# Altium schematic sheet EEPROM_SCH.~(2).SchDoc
size D
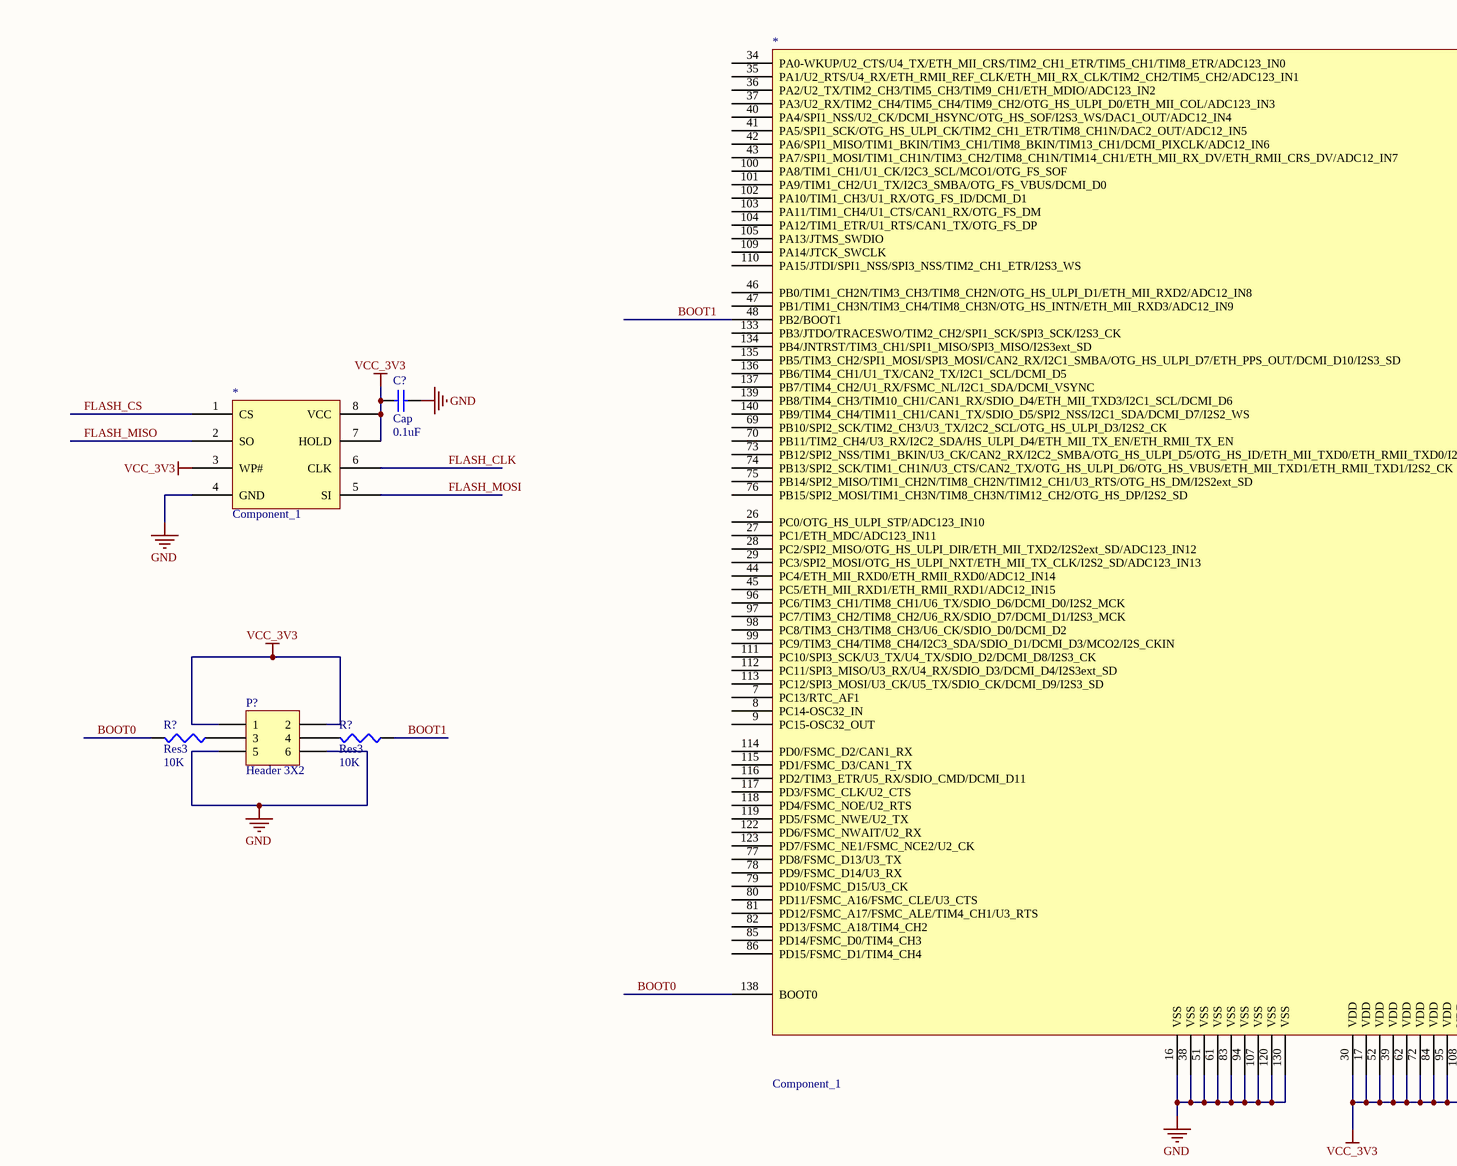
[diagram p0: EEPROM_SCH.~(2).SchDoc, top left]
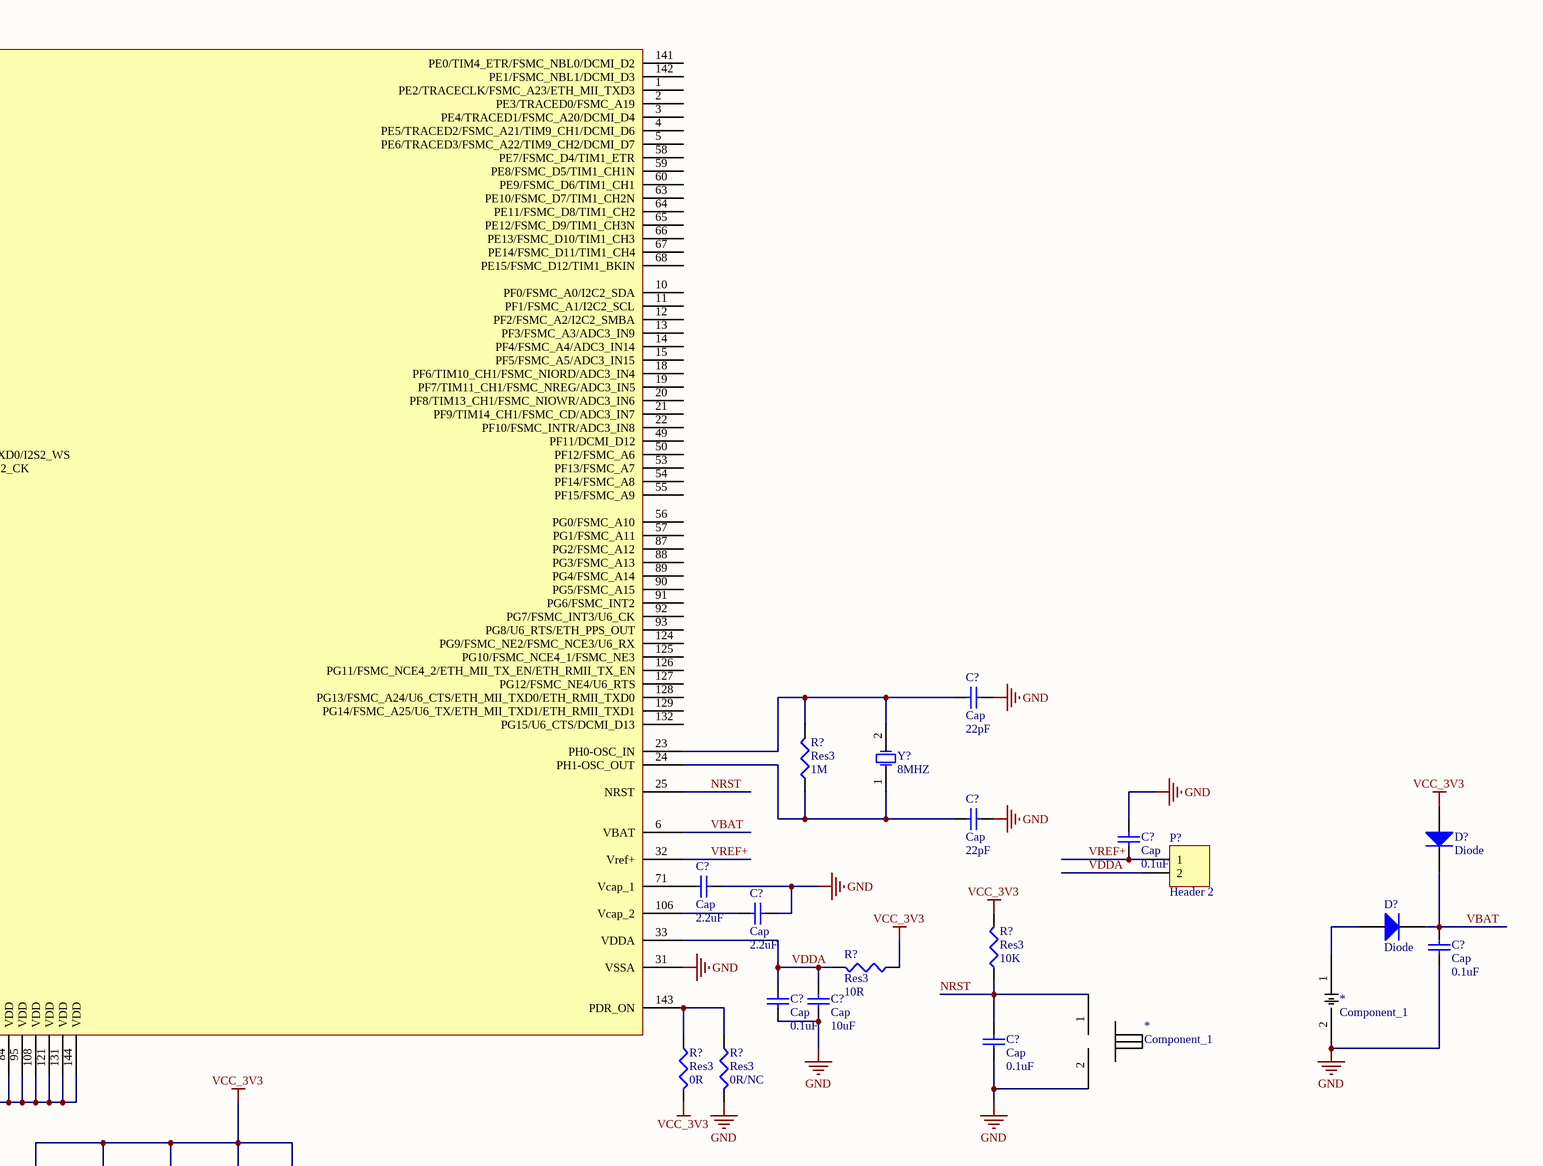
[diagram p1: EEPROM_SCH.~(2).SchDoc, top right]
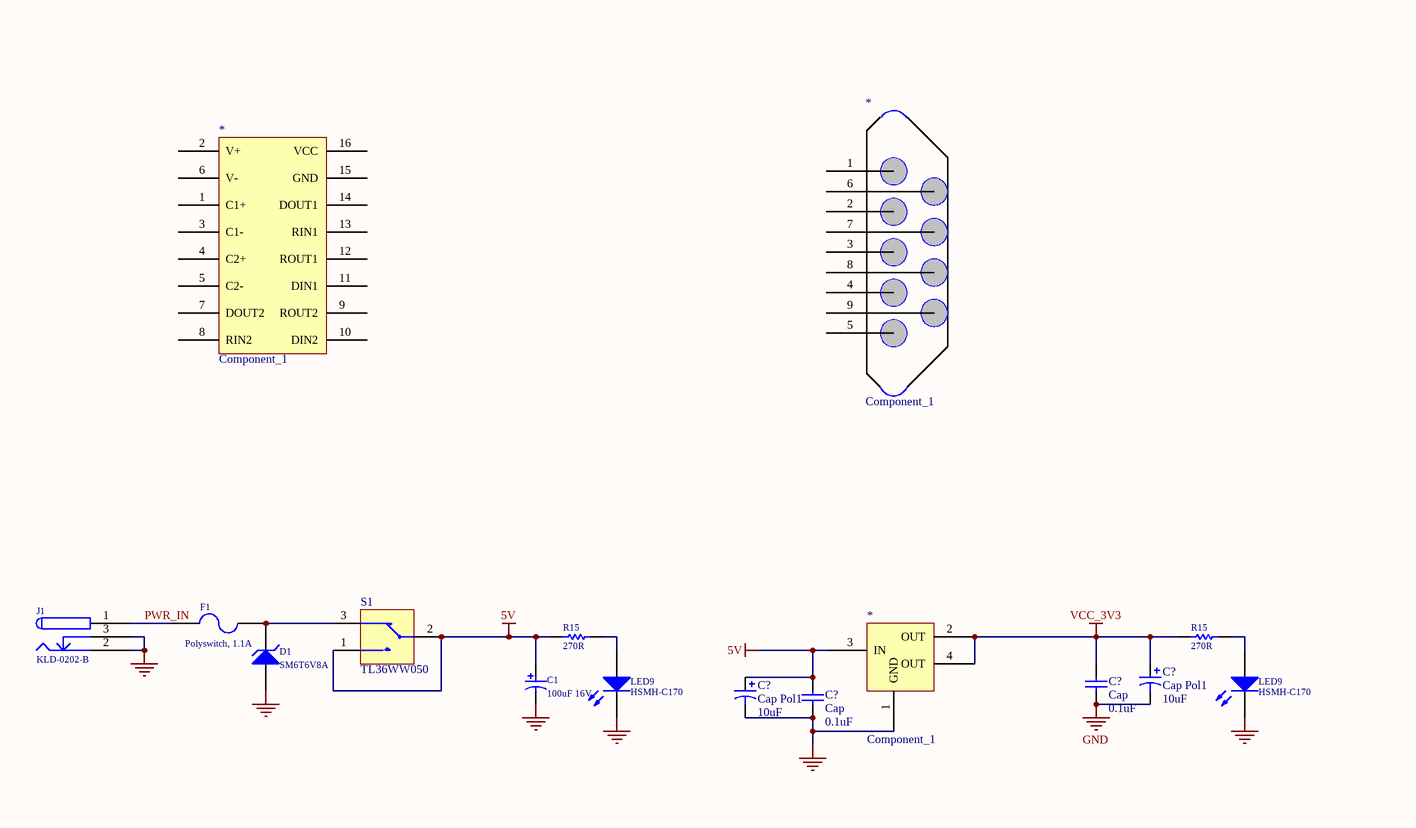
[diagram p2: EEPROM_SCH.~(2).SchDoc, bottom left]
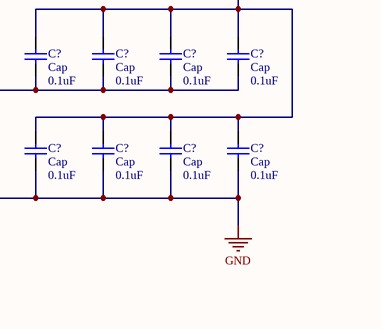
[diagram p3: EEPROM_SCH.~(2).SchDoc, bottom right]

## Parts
(Parts that share a designator on the sheet are numbered #1, #2 ... from top to bottom, then left to right.)
*#1  Component_1
*#2  Component_1
*#3  Component_1
*#4  Component_1
*#5  Component_1
*#6  Component_1
*#7  Component_1
C1  100uF 16V  [CAPPR2-5X6.8]
C?#1  Cap  value 0.1uF  [RAD-0.3]
C?#2  Cap  value 22pF  [RAD-0.3]
C?#3  Cap  value 22pF  [RAD-0.3]
C?#4  Cap  value 0.1uF  [RAD-0.3]
C?#5  Cap  value 2.2uF  [RAD-0.3]
C?#6  Cap  value 2.2uF  [RAD-0.3]
C?#7  Cap  value 0.1uF  [RAD-0.3]
C?#8  Cap  value 0.1uF  [RAD-0.3]
C?#9  Cap  value 10uF  [RAD-0.3]
C?#10  Cap  value 0.1uF  [RAD-0.3]
C?#11  Cap  value 0.1uF  [RAD-0.3]
C?#12  Cap  value 0.1uF  [RAD-0.3]
C?#13  Cap  value 0.1uF  [RAD-0.3]
C?#14  Cap  value 0.1uF  [RAD-0.3]
C?#15  Cap  value 0.1uF  [RAD-0.3]
C?#16  Cap  value 0.1uF  [RAD-0.3]
C?#17  Cap  value 0.1uF  [RAD-0.3]
C?#18  Cap  value 0.1uF  [RAD-0.3]
C?#19  Cap  value 0.1uF  [RAD-0.3]
C?#20  Cap Pol1  value 10uF  [RB7.6-15]
C?#21  Cap Pol1  value 10uF  [RB7.6-15]
C?#22  Cap  value 0.1uF  [RAD-0.3]
D1  SM6T6V8A  [DO214]
D?#1  Diode  [SMC]
D?#2  Diode  [SMC]
F1  Polyswitch, 1.1A  [RUE160_0.2]
J1  KLD-0202-B  [KLD-0202]
LED9#1  HSMH-C170  [SMD _LED]
LED9#2  HSMH-C170  [SMD _LED]
P?#1  Header 3X2  [HDR2X3]
P?#2  Header 2  [HDR1X2]
R15#1  270R  [CR2012-0805]
R15#2  270R  [CR2012-0805]
R?#1  Res3  value 10K  [J1-0603]
R?#2  Res3  value 10K  [J1-0603]
R?#3  Res3  value 1M  [J1-0603]
R?#4  Res3  value 10K  [J1-0603]
R?#5  Res3  value 10R  [J1-0603]
R?#6  Res3  value 0R  [J1-0603]
R?#7  Res3  value 0R/NC  [J1-0603]
S1  TL36WW050  [PCB_SWITCH]
Y?  8MHZ  [R38]

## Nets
5V: *#7.3(IN) C1.1 C?#21.1 C?#22.1 R15#1.2 S1.1 S1.2
GND: *#1.16(VSS) *#1.31(VSSA) *#1.38(VSS) *#1.51(VSS) *#1.61(VSS) *#1.83(VSS) *#1.94(VSS) *#1.107(VSS) *#1.120(VSS) *#1.130(VSS) *#2.4(GND) *#3.2 *#4.2 *#7.1(GND) C1.2 C?#1.2 C?#2.1 C?#3.1 C?#4.1 C?#5.2 C?#6.2 C?#7.2 C?#8.2 C?#9.2 C?#10.2 C?#11.1 C?#12.1 C?#13.1 C?#14.1 C?#15.1 C?#16.1 C?#17.1 C?#18.1 C?#19.2 C?#20.2 C?#21.2 C?#22.2 D1.1(A) J1.2 J1.3 LED9#1.2(K) LED9#2.2(K) P?#1.5 P?#1.6 R?#7.2
VCC_3V3: *#1.17(VDD) *#1.30(VDD) *#1.39(VDD) *#1.52(VDD) *#1.62(VDD) *#1.72(VDD) *#1.84(VDD) *#1.95(VDD) *#1.108(VDD) *#1.121(VDD) *#1.131(VDD) *#1.144(VDD) *#2.3(WP#) *#2.7(HOLD) *#2.8(VCC) *#7.2(OUT) *#7.4(OUT) C?#1.1 C?#11.2 C?#12.2 C?#13.2 C?#14.2 C?#15.2 C?#16.2 C?#17.2 C?#18.2 C?#19.1 C?#20.1 D?#1.1(A) P?#1.1 P?#1.2 R15#2.2 R?#4.2 R?#5.1 R?#6.2
BOOT0: *#1.138(BOOT0) R?#1.2
BOOT1: *#1.48(PB2/BOOT1) R?#2.1
FLASH_CLK: *#2.6(CLK)
FLASH_CS: *#2.1(CS)
FLASH_MISO: *#2.2(SO)
FLASH_MOSI: *#2.5(SI)
NRST: *#1.25(NRST) *#3.1 C?#10.1 R?#4.1
PWR_IN: F1.1 J1.1
VBAT: *#1.6(VBAT) C?#7.1 D?#1.2(K) D?#2.2(K)
VDDA: *#1.33(VDDA) C?#8.1 C?#9.1 P?#2.2 R?#5.2
VREF+: *#1.32(Vref+) C?#4.2 P?#2.1
Net*#1_23: *#1.23(PH0-OSC_IN) C?#2.2 R?#3.2 Y?.2(OSC2)
Net*#1_24: *#1.24(PH1-OSC_OUT) C?#3.2 R?#3.1 Y?.1(OSC1)
Net*#1_71: *#1.71(Vcap_1) C?#5.1
Net*#1_106: *#1.106(Vcap_2) C?#6.1
Net*#1_143: *#1.143(PDR_ON) R?#6.1 R?#7.1
Net*#4_1: *#4.1 D?#2.1(A)
NetD1_2: D1.2(K) F1.2 S1.3
NetLED9#1_1: LED9#1.1(A) R15#1.1
NetLED9#2_1: LED9#2.1(A) R15#2.1
NetP?#1_3: P?#1.3 R?#1.1
NetP?#1_4: P?#1.4 R?#2.2

Not connected (* = marked no-connect by the designer): *#1 1(PE2/TRACECLK/FSMC_A23/ETH_MII_TXD3) 2(PE3/TRACED0/FSMC_A19) 3(PE4/TRACED1/FSMC_A20/DCMI_D4) 4(PE5/TRACED2/FSMC_A21/TIM9_CH1/DCMI_D6) 5(PE6/TRACED3/FSMC_A22/TIM9_CH2/DCMI_D7) 7(PC13/RTC_AF1) 8(PC14-OSC32_IN) 9(PC15-OSC32_OUT) 10(PF0/FSMC_A0/I2C2_SDA) 11(PF1/FSMC_A1/I2C2_SCL) 12(PF2/FSMC_A2/I2C2_SMBA) 13(PF3/FSMC_A3/ADC3_IN9) 14(PF4/FSMC_A4/ADC3_IN14) 15(PF5/FSMC_A5/ADC3_IN15) 18(PF6/TIM10_CH1/FSMC_NIORD/ADC3_IN4) 19(PF7/TIM11_CH1/FSMC_NREG/ADC3_IN5) 20(PF8/TIM13_CH1/FSMC_NIOWR/ADC3_IN6) 21(PF9/TIM14_CH1/FSMC_CD/ADC3_IN7) 22(PF10/FSMC_INTR/ADC3_IN8) 26(PC0/OTG_HS_ULPI_STP/ADC123_IN10) 27(PC1/ETH_MDC/ADC123_IN11) 28(PC2/SPI2_MISO/OTG_HS_ULPI_DIR/ETH_MII_TXD2/I2S2ext_SD/ADC123_IN12) 29(PC3/SPI2_MOSI/OTG_HS_ULPI_NXT/ETH_MII_TX_CLK/I2S2_SD/ADC123_IN13) 34(PA0-WKUP/U2_CTS/U4_TX/ETH_MII_CRS/TIM2_CH1_ETR/TIM5_CH1/TIM8_ETR/ADC123_IN0) 35(PA1/U2_RTS/U4_RX/ETH_RMII_REF_CLK/ETH_MII_RX_CLK/TIM2_CH2/TIM5_CH2/ADC123_IN1) 36(PA2/U2_TX/TIM2_CH3/TIM5_CH3/TIM9_CH1/ETH_MDIO/ADC123_IN2) 37(PA3/U2_RX/TIM2_CH4/TIM5_CH4/TIM9_CH2/OTG_HS_ULPI_D0/ETH_MII_COL/ADC123_IN3) 40(PA4/SPI1_NSS/U2_CK/DCMI_HSYNC/OTG_HS_SOF/I2S3_WS/DAC1_OUT/ADC12_IN4) 41(PA5/SPI1_SCK/OTG_HS_ULPI_CK/TIM2_CH1_ETR/TIM8_CH1N/DAC2_OUT/ADC12_IN5) 42(PA6/SPI1_MISO/TIM1_BKIN/TIM3_CH1/TIM8_BKIN/TIM13_CH1/DCMI_PIXCLK/ADC12_IN6) 43(PA7/SPI1_MOSI/TIM1_CH1N/TIM3_CH2/TIM8_CH1N/TIM14_CH1/ETH_MII_RX_DV/ETH_RMII_CRS_DV/ADC12_IN7) 44(PC4/ETH_MII_RXD0/ETH_RMII_RXD0/ADC12_IN14) 45(PC5/ETH_MII_RXD1/ETH_RMII_RXD1/ADC12_IN15) 46(PB0/TIM1_CH2N/TIM3_CH3/TIM8_CH2N/OTG_HS_ULPI_D1/ETH_MII_RXD2/ADC12_IN8) 47(PB1/TIM1_CH3N/TIM3_CH4/TIM8_CH3N/OTG_HS_INTN/ETH_MII_RXD3/ADC12_IN9) 49(PF11/DCMI_D12) 50(PF12/FSMC_A6) 53(PF13/FSMC_A7) 54(PF14/FSMC_A8) 55(PF15/FSMC_A9) 56(PG0/FSMC_A10) 57(PG1/FSMC_A11) 58(PE7/FSMC_D4/TIM1_ETR) 59(PE8/FSMC_D5/TIM1_CH1N) 60(PE9/FSMC_D6/TIM1_CH1) 63(PE10/FSMC_D7/TIM1_CH2N) 64(PE11/FSMC_D8/TIM1_CH2) 65(PE12/FSMC_D9/TIM1_CH3N) 66(PE13/FSMC_D10/TIM1_CH3) 67(PE14/FSMC_D11/TIM1_CH4) 68(PE15/FSMC_D12/TIM1_BKIN) 69(PB10/SPI2_SCK/TIM2_CH3/U3_TX/I2C2_SCL/OTG_HS_ULPI_D3/I2S2_CK) 70(PB11/TIM2_CH4/U3_RX/I2C2_SDA/HS_ULPI_D4/ETH_MII_TX_EN/ETH_RMII_TX_EN) 73(PB12/SPI2_NSS/TIM1_BKIN/U3_CK/CAN2_RX/I2C2_SMBA/OTG_HS_ULPI_D5/OTG_HS_ID/ETH_MII_TXD0/ETH_RMII_TXD0/I2S2_WS) 74(PB13/SPI2_SCK/TIM1_CH1N/U3_CTS/CAN2_TX/OTG_HS_ULPI_D6/OTG_HS_VBUS/ETH_MII_TXD1/ETH_RMII_TXD1/I2S2_CK) 75(PB14/SPI2_MISO/TIM1_CH2N/TIM8_CH2N/TIM12_CH1/U3_RTS/OTG_HS_DM/I2S2ext_SD) 76(PB15/SPI2_MOSI/TIM1_CH3N/TIM8_CH3N/TIM12_CH2/OTG_HS_DP/I2S2_SD) 77(PD8/FSMC_D13/U3_TX) 78(PD9/FSMC_D14/U3_RX) 79(PD10/FSMC_D15/U3_CK) 80(PD11/FSMC_A16/FSMC_CLE/U3_CTS) 81(PD12/FSMC_A17/FSMC_ALE/TIM4_CH1/U3_RTS) 82(PD13/FSMC_A18/TIM4_CH2) 85(PD14/FSMC_D0/TIM4_CH3) 86(PD15/FSMC_D1/TIM4_CH4) 87(PG2/FSMC_A12) 88(PG3/FSMC_A13) 89(PG4/FSMC_A14) 90(PG5/FSMC_A15) 91(PG6/FSMC_INT2) 92(PG7/FSMC_INT3/U6_CK) 93(PG8/U6_RTS/ETH_PPS_OUT) 96(PC6/TIM3_CH1/TIM8_CH1/U6_TX/SDIO_D6/DCMI_D0/I2S2_MCK) 97(PC7/TIM3_CH2/TIM8_CH2/U6_RX/SDIO_D7/DCMI_D1/I2S3_MCK) 98(PC8/TIM3_CH3/TIM8_CH3/U6_CK/SDIO_D0/DCMI_D2) 99(PC9/TIM3_CH4/TIM8_CH4/I2C3_SDA/SDIO_D1/DCMI_D3/MCO2/I2S_CKIN) 100(PA8/TIM1_CH1/U1_CK/I2C3_SCL/MCO1/OTG_FS_SOF) 101(PA9/TIM1_CH2/U1_TX/I2C3_SMBA/OTG_FS_VBUS/DCMI_D0) 102(PA10/TIM1_CH3/U1_RX/OTG_FS_ID/DCMI_D1) 103(PA11/TIM1_CH4/U1_CTS/CAN1_RX/OTG_FS_DM) 104(PA12/TIM1_ETR/U1_RTS/CAN1_TX/OTG_FS_DP) 105(PA13/JTMS_SWDIO) 109(PA14/JTCK_SWCLK) 110(PA15/JTDI/SPI1_NSS/SPI3_NSS/TIM2_CH1_ETR/I2S3_WS) 111(PC10/SPI3_SCK/U3_TX/U4_TX/SDIO_D2/DCMI_D8/I2S3_CK) 112(PC11/SPI3_MISO/U3_RX/U4_RX/SDIO_D3/DCMI_D4/I2S3ext_SD) 113(PC12/SPI3_MOSI/U3_CK/U5_TX/SDIO_CK/DCMI_D9/I2S3_SD) 114(PD0/FSMC_D2/CAN1_RX) 115(PD1/FSMC_D3/CAN1_TX) 116(PD2/TIM3_ETR/U5_RX/SDIO_CMD/DCMI_D11) 117(PD3/FSMC_CLK/U2_CTS) 118(PD4/FSMC_NOE/U2_RTS) 119(PD5/FSMC_NWE/U2_TX) 122(PD6/FSMC_NWAIT/U2_RX) 123(PD7/FSMC_NE1/FSMC_NCE2/U2_CK) 124(PG9/FSMC_NE2/FSMC_NCE3/U6_RX) 125(PG10/FSMC_NCE4_1/FSMC_NE3) 126(PG11/FSMC_NCE4_2/ETH_MII_TX_EN/ETH_RMII_TX_EN) 127(PG12/FSMC_NE4/U6_RTS) 128(PG13/FSMC_A24/U6_CTS/ETH_MII_TXD0/ETH_RMII_TXD0) 129(PG14/FSMC_A25/U6_TX/ETH_MII_TXD1/ETH_RMII_TXD1) 132(PG15/U6_CTS/DCMI_D13) 133(PB3/JTDO/TRACESWO/TIM2_CH2/SPI1_SCK/SPI3_SCK/I2S3_CK) 134(PB4/JNTRST/TIM3_CH1/SPI1_MISO/SPI3_MISO/I2S3ext_SD) 135(PB5/TIM3_CH2/SPI1_MOSI/SPI3_MOSI/CAN2_RX/I2C1_SMBA/OTG_HS_ULPI_D7/ETH_PPS_OUT/DCMI_D10/I2S3_SD) 136(PB6/TIM4_CH1/U1_TX/CAN2_TX/I2C1_SCL/DCMI_D5) 137(PB7/TIM4_CH2/U1_RX/FSMC_NL/I2C1_SDA/DCMI_VSYNC) 139(PB8/TIM4_CH3/TIM10_CH1/CAN1_RX/SDIO_D4/ETH_MII_TXD3/I2C1_SCL/DCMI_D6) 140(PB9/TIM4_CH4/TIM11_CH1/CAN1_TX/SDIO_D5/SPI2_NSS/I2C1_SDA/DCMI_D7/I2S2_WS) 141(PE0/TIM4_ETR/FSMC_NBL0/DCMI_D2) 142(PE1/FSMC_NBL1/DCMI_D3); *#5 1(C1+) 2(V+) 3(C1-) 4(C2+) 5(C2-) 6(V-) 7(DOUT2) 8(RIN2) 9(ROUT2) 10(DIN2) 11(DIN1) 12(ROUT1) 13(RIN1) 14(DOUT1) 15(GND) 16(VCC); *#6 1 2 3 4 5 6 7 8 9

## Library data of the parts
C1 = CAP_POLAR_1: Polar Capacitor
C?#1-C?#19 C?#22 = Cap: Capacitor
C?#20 C?#21 = Cap Pol1: Polarized Capacitor (Radial)
D1 = BZG03C13: Zener Diode, 6.2V, 5W; Manufacturer: Microsemi
D?#1 D?#2 = Diode: Default Diode
F1 = Fuse 2: Polyswitch 1.1A, Raychem RUE110
J1 = KLD-0202-B: Low Voltage Power Supply Connector; Manufacturer: Kycon; AEMS Code: 3510211
LED9#1 LED9#2 = HSMX-C670: Typical RED GaAs SMD LED Agilent make; AEMS Code: 2610081
P?#1 = Header 3X2: Header, 3-Pin, Dual row
P?#2 = Header 2: Header, 2-Pin
R15#1 R15#2 = RES: Resistor; AEMS Code: 1200430
R?#1-R?#7 = Res3: Resistor
S1 = PCB_MOUNT_SWITCH: SPDT Subminiature Toggle Switch
Y? = XTAL: Crystal Oscillator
